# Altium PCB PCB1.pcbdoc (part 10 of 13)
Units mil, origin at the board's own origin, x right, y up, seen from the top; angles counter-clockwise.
Board outline 5895.51 x 5895.51 mil, 8 copper layers (Top Layer, L2_GND1, L3_SIG1, L4_GND2, L5_PWR, L6_SIG2, L7_GND3, Bottom Layer), stack 63.761 mil thick; 673 components, 558 nets, 2797 pads, 1861 vias.
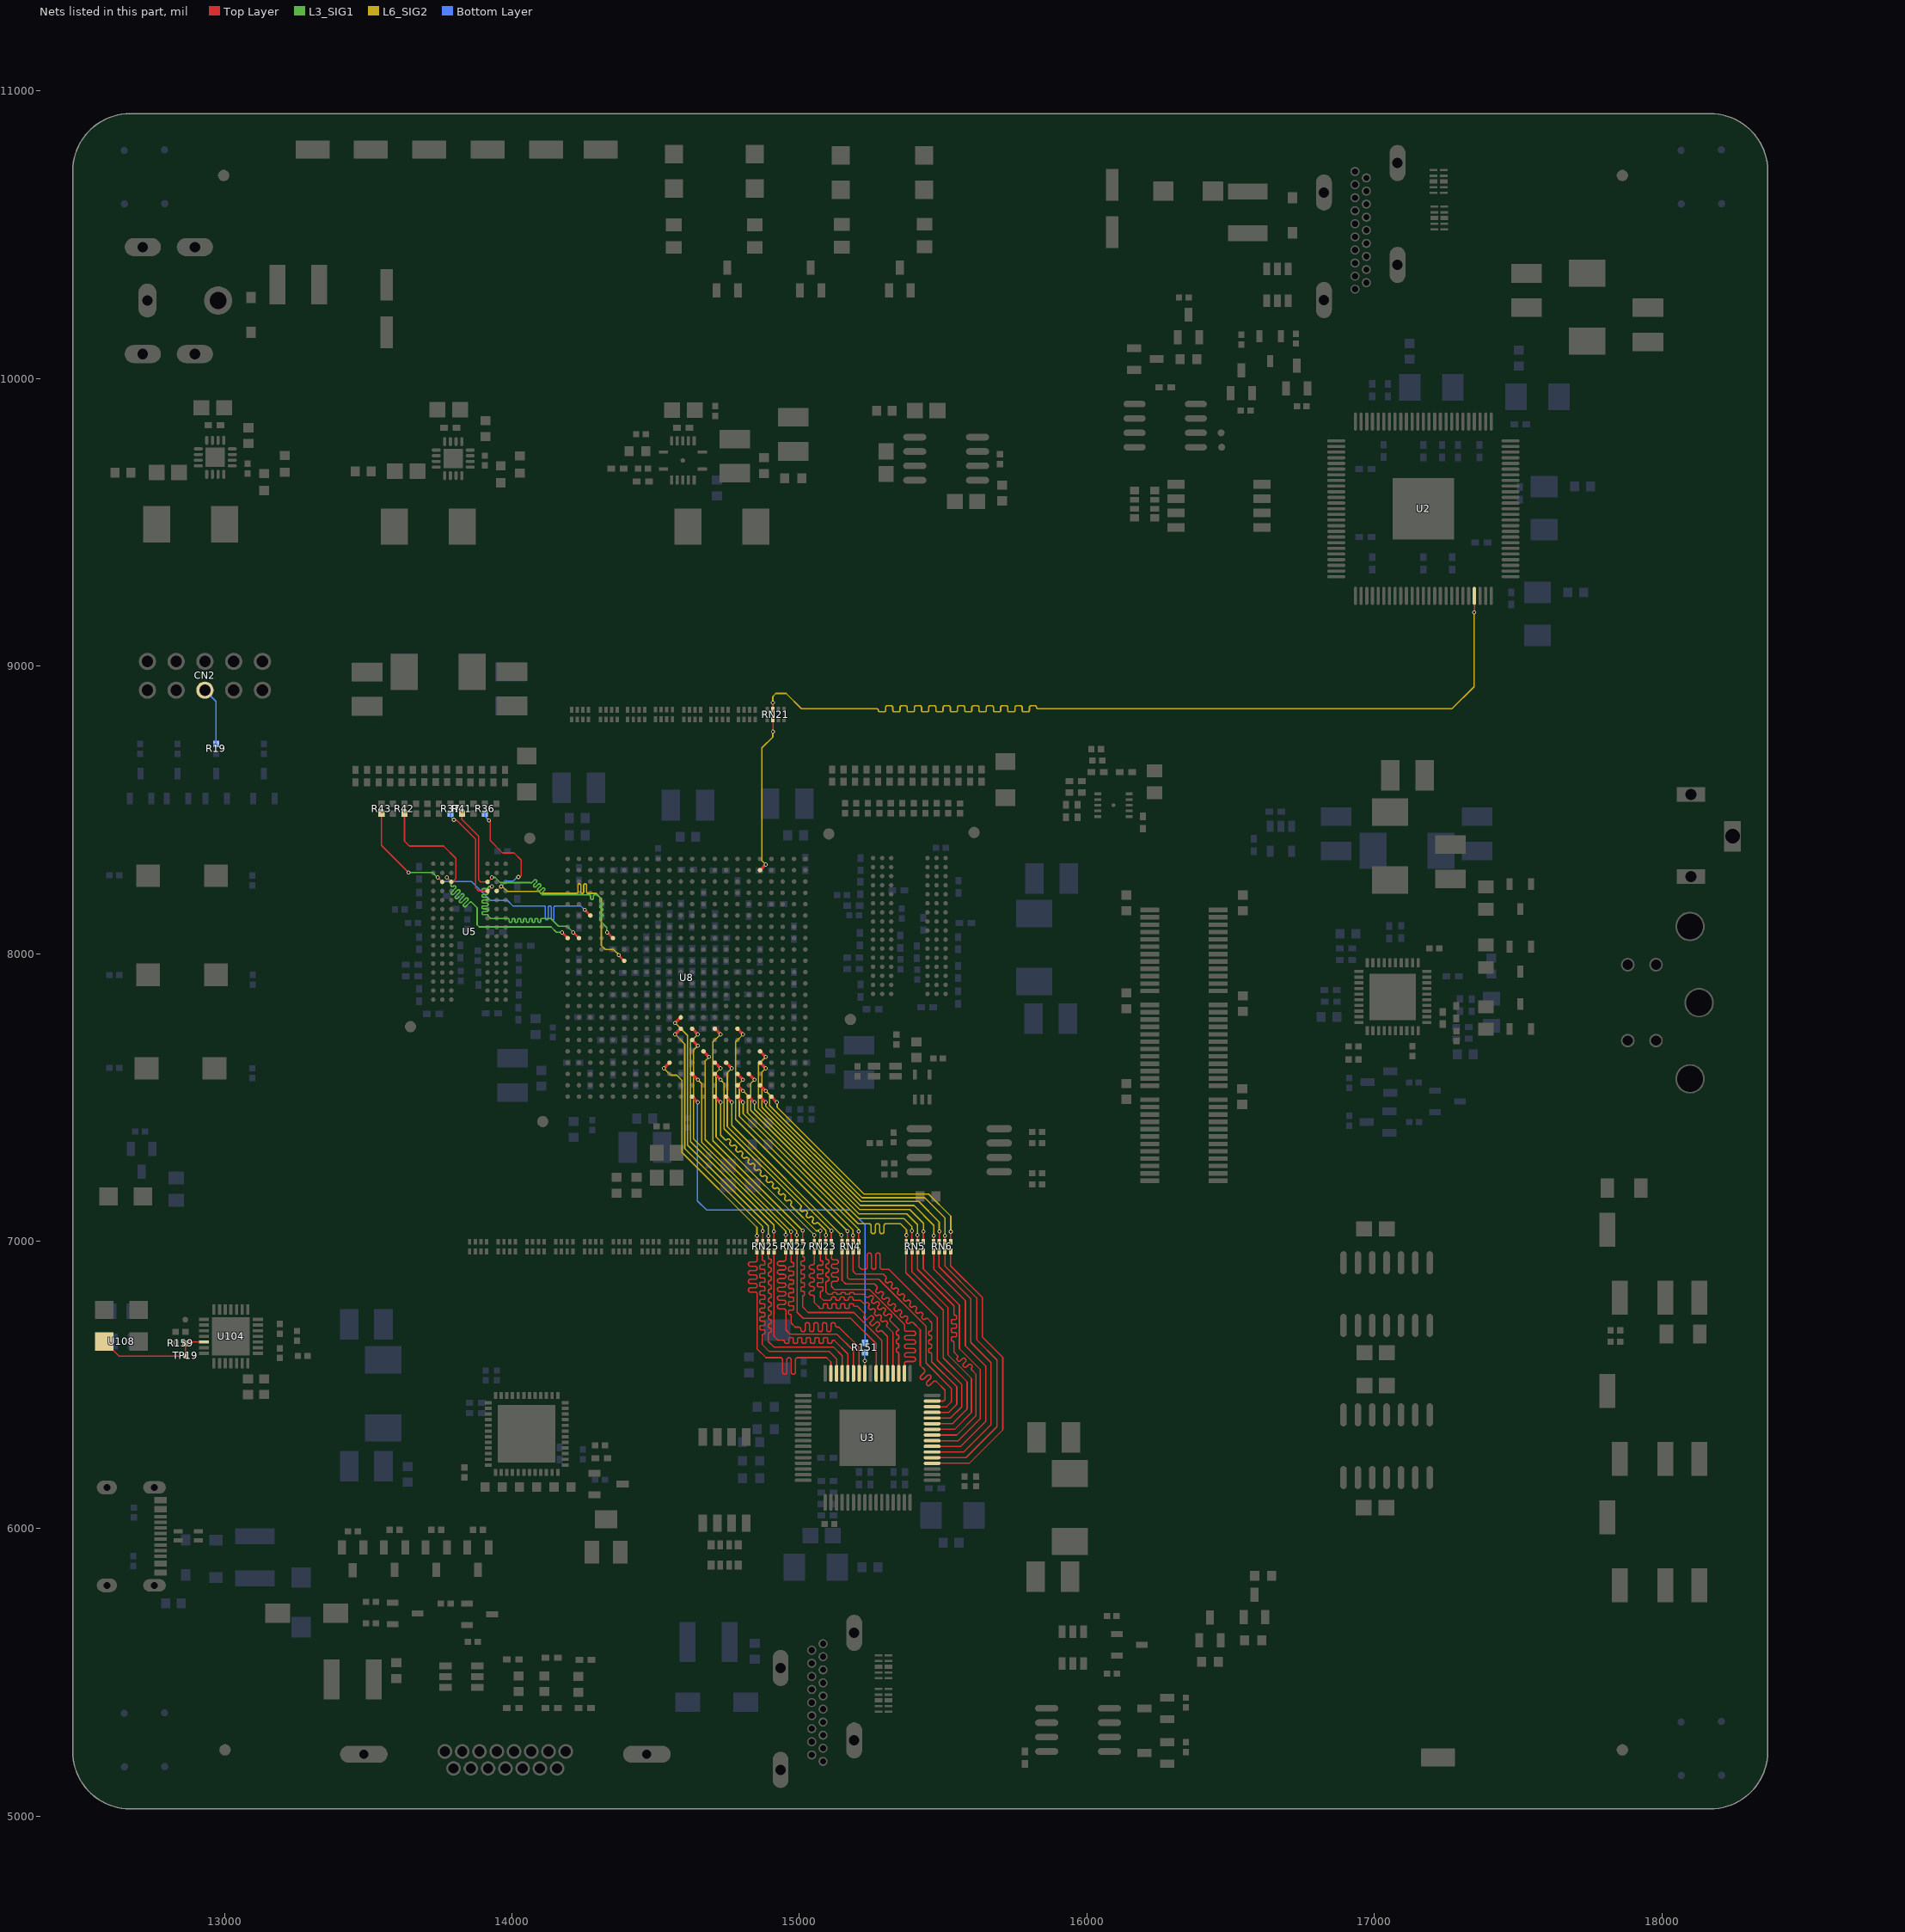
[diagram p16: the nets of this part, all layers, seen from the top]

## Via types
v1: diameter 23.62, hole 15.75, Top Layer to Bottom Layer, 621 vias
v2: diameter 13.8, hole 7.9, Top Layer to Bottom Layer, 567 vias
v3: diameter 13.78, hole 7.87, Top Layer to Bottom Layer, 529 vias
v4: diameter 13.78, hole 7.9, Top Layer to Bottom Layer, 114 vias
v5: diameter 15.75, hole 7.87, Top Layer to Bottom Layer, 16 vias
v6: diameter 24, hole 12, Top Layer to Bottom Layer, 10 vias
v7: diameter 11.81, hole 7.87, Top Layer to Bottom Layer, 4 vias

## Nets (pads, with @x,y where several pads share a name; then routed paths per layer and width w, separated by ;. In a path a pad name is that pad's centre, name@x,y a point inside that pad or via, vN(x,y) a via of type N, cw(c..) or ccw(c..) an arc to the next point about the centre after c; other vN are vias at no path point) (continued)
TFP401_VSYNC: RN21.6 U2.47 | length 3204.1
  Top Layer w4.7: RN21.6@14907.52,8847.83 v3(14907.52,8873) ; v4(17346.36,9187) 17348.01,9188.65 U2.47@17348.01,9232.15
  L6_SIG2 w5: v3(14907.52,8873) 14907.52,8893.88 14918.08,8904.44 14953.96,8904.44 15007.24,8851.17 15269.64,8851.17 cw(c15269.64,8845.96) 15274.85,8845.96 ccw(c15280.06,8845.96) 15280.06,8840.74 15294.64,8840.74 ccw(c15294.64,8845.96) 15299.85,8845.96 15299.85,8856.38 cw(c15305.06,8856.38) 15305.06,8861.59 15319.64,8861.59 cw(c15319.64,8856.38) 15324.85,8856.38 15324.85,8845.96 ccw(c15330.06,8845.96) 15330.06,8840.74 15344.64,8840.74 ccw(c15344.64,8845.96) 15349.85,8845.96 15349.85,8856.38 cw(c15355.06,8856.38) 15355.06,8861.59 15369.64,8861.59 cw(c15369.64,8856.38) 15374.85,8856.38 15374.85,8845.96 ccw(c15380.06,8845.96) 15380.06,8840.74 15394.64,8840.74 ccw(c15394.64,8845.96) 15399.85,8845.96 15399.85,8856.38 cw(c15405.06,8856.38) 15405.06,8861.59 15419.64,8861.59 cw(c15419.64,8856.38) 15424.85,8856.38 15424.85,8845.96 ccw(c15430.06,8845.96) 15430.06,8840.74 15444.64,8840.74 ccw(c15444.64,8845.96) 15449.85,8845.96 15449.85,8856.38 cw(c15455.06,8856.38) 15455.06,8861.59 15469.64,8861.59 cw(c15469.64,8856.38) 15474.85,8856.38 15474.85,8845.96 ccw(c15480.06,8845.96) 15480.06,8840.74 15494.64,8840.74 ccw(c15494.64,8845.96) 15499.85,8845.96 15499.85,8856.38 cw(c15505.06,8856.38) 15505.06,8861.59 15519.64,8861.59 cw(c15519.64,8856.38) 15524.85,8856.38 15524.85,8845.96 ccw(c15530.06,8845.96) 15530.06,8840.74 15544.64,8840.74 ccw(c15544.64,8845.96) 15549.85,8845.96 15549.85,8856.38 cw(c15555.06,8856.38) 15555.06,8861.59 15569.64,8861.59 cw(c15569.64,8856.38) 15574.85,8856.38 15574.85,8845.96 ccw(c15580.06,8845.96) 15580.06,8840.74 15594.64,8840.74 ccw(c15594.64,8845.96) 15599.85,8845.96 15599.85,8856.38 cw(c15605.06,8856.38) 15605.06,8861.59 15619.64,8861.59 cw(c15619.64,8856.38) 15624.85,8856.38 15624.85,8845.96 ccw(c15630.06,8845.96) 15630.06,8840.74 15644.64,8840.74 ccw(c15644.64,8845.96) 15649.85,8845.96 15649.85,8856.38 cw(c15655.06,8856.38) 15655.06,8861.59 15669.64,8861.59 cw(c15669.64,8856.38) 15674.85,8856.38 15674.85,8845.96 ccw(c15680.06,8845.96) 15680.06,8840.74 15694.64,8840.74 ccw(c15694.64,8845.96) 15699.85,8845.96 15699.85,8856.38 cw(c15705.06,8856.38) 15705.06,8861.59 15719.64,8861.59 cw(c15719.64,8856.38) 15724.85,8856.38 15724.85,8845.96 ccw(c15730.06,8845.96) 15730.06,8840.74 15744.64,8840.74 ccw(c15744.64,8845.96) 15749.85,8845.96 15749.85,8856.38 cw(c15755.06,8856.38) 15755.06,8861.59 15769.64,8861.59 cw(c15769.64,8856.38) 15774.85,8856.38 15774.85,8845.96 ccw(c15780.06,8845.96) 15780.06,8840.74 15794.64,8840.74 ccw(c15794.64,8845.96) 15799.85,8845.96 15799.85,8856.38 cw(c15805.06,8856.38) 15805.06,8861.59 15819.64,8861.59 cw(c15819.64,8856.38) 15824.85,8856.38 ccw(c15830.06,8856.38) 15830.06,8851.17 17269.84,8851.17 17346.48,8927.81 17346.48,8961.68 17346.36,8961.81 ; 17346.27,8961.9 17346.36,8961.81 ; v4(17346.36,9187) 17346.36,8961.81
TFP401_VSYNC_FPGA: RN21.3 U8.B18 | length 553.7
  Top Layer w4.7: RN21.3@14907.52,8814.17 14907.75,8813.93 v3(14907.75,8771.68)
  Top Layer w10: U8.B18@14863.26,8290.01 v2(14882.94,8309.69)
  L6_SIG2 w5: v2(14882.94,8309.69) 14869.67,8322.96 14869.67,8715.65 14907.41,8753.39 14907.41,8771.34 v3(14907.75,8771.68)
TFP410_CLK: R151.1 U3.57 | length 72.8
  Top Layer w4.7: U3.57@15225.56,6541.29 15227.36,6543.08 v3(15227.36,6584)
  Bottom Layer w4.7: v3(15227.36,6584) 15227.36,6611.96 R151.1@15228.36,6612.96
TFP410_CLK_FPGA: R151.2 U8.AB12 | length 1398.7
  Top Layer w10: U8.AB12@14627.06,7502.6 v2(14646.74,7482.92)
  Bottom Layer w4.7: v2(14646.74,7482.92) 14645.36,7481.54 14645.36,7140 14676.36,7109 15176.36,7109 15228.36,7057 R151.2@15228.36,6647.04
TFP410_D0: RN25.8 U3.63 | length 1056
  Top Layer w4.7: RN25.8@14852.83,6964.17 14853.36,6963.64 14853.36,6935.12 cw(c14845.86,6935.12) 14845.86,6927.62 14829.86,6927.62 ccw(c14829.86,6920.12) 14829.86,6912.62 14845.86,6912.62 cw(c14845.86,6905.12) 14845.86,6897.62 14829.86,6897.62 ccw(c14829.86,6890.12) 14829.86,6882.62 14845.86,6882.62 cw(c14845.86,6875.12) 14845.86,6867.62 14829.86,6867.62 ccw(c14829.86,6860.12) 14829.86,6852.62 14845.86,6852.62 cw(c14845.86,6845.12) 14845.86,6837.62 14829.86,6837.62 ccw(c14829.86,6830.12) 14829.86,6822.62 14845.86,6822.62 cw(c14845.86,6815.12) 14853.36,6815.12 14853.36,6625 14883.36,6595 14933.74,6595 cw(c14933.74,6587.5) 14941.24,6587.5 14941.24,6544.59 ccw(c14948.74,6544.59) 14956.24,6544.59 14956.24,6587.5 cw(c14963.74,6587.5) 14971.24,6587.5 14971.24,6544.59 ccw(c14978.74,6544.59) 14986.24,6544.59 14986.24,6587.5 cw(c14993.74,6587.5) 14993.74,6595 15094.36,6595 15109.41,6579.95 U3.63@15109.41,6540.41
TFP410_D0_FPGA: RN25.1 U8.W10 | length 777.4
  Top Layer w4.7: v3(14852.36,7019) 14852.83,7018.53 RN25.1@14852.83,6997.83
  Top Layer w10: v2(14528.63,7601.05) U8.W10@14548.3,7620.73
  L6_SIG2 w5: v2(14528.63,7601.05) 14552.68,7577 14573.36,7577 14591.36,7559 14591.36,7309 14852.36,7048 v3(14852.36,7019)
TFP410_D1: RN25.7 U3.62 | length 889.9
  Top Layer w4.7: RN25.7@14872.52,6964.17 14871.36,6963.01 14871.36,6936.43 ccw(c14875.86,6936.43) 14875.86,6931.93 cw(c14875.86,6927.43) 14880.36,6927.43 14880.36,6921.43 cw(c14875.86,6921.43) 14875.86,6916.93 14866.86,6916.93 ccw(c14866.86,6912.43) 14862.36,6912.43 14862.36,6906.43 ccw(c14866.86,6906.43) 14866.86,6901.93 14875.86,6901.93 cw(c14875.86,6897.43) 14880.36,6897.43 14880.36,6891.43 cw(c14875.86,6891.43) 14875.86,6886.93 14866.86,6886.93 ccw(c14866.86,6882.43) 14862.36,6882.43 14862.36,6876.43 ccw(c14866.86,6876.43) 14866.86,6871.93 14875.86,6871.93 cw(c14875.86,6867.43) 14880.36,6867.43 14880.36,6861.43 cw(c14875.86,6861.43) 14875.86,6856.93 14866.86,6856.93 ccw(c14866.86,6852.43) 14862.36,6852.43 14862.36,6846.43 ccw(c14866.86,6846.43) 14866.86,6841.93 14875.86,6841.93 cw(c14875.86,6837.43) 14880.36,6837.43 14880.36,6831.43 cw(c14875.86,6831.43) 14875.86,6826.93 14866.86,6826.93 ccw(c14866.86,6822.43) 14862.36,6822.43 14862.36,6816.43 ccw(c14866.86,6816.43) 14866.86,6811.93 14875.86,6811.93 cw(c14875.86,6807.43) 14880.36,6807.43 14880.36,6801.43 cw(c14875.86,6801.43) 14875.86,6796.93 14866.86,6796.93 ccw(c14866.86,6792.43) 14862.36,6792.43 14862.36,6786.43 ccw(c14866.86,6786.43) 14866.86,6781.93 14875.86,6781.93 cw(c14875.86,6777.43) 14880.36,6777.43 14880.36,6771.43 cw(c14875.86,6771.43) 14875.86,6766.93 14866.86,6766.93 ccw(c14866.86,6762.43) 14862.36,6762.43 14862.36,6756.43 ccw(c14866.86,6756.43) 14866.86,6751.93 14875.86,6751.93 cw(c14875.86,6747.43) 14880.36,6747.43 14880.36,6741.43 cw(c14875.86,6741.43) 14875.86,6736.93 14866.86,6736.93 ccw(c14866.86,6732.43) 14862.36,6732.43 14862.36,6726.43 ccw(c14866.86,6726.43) 14866.86,6721.93 14875.86,6721.93 cw(c14875.86,6717.43) 14880.36,6717.43 14880.36,6711.43 cw(c14875.86,6711.43) 14875.86,6706.93 14866.86,6706.93 ccw(c14866.86,6702.43) 14862.36,6702.43 14862.36,6696.43 ccw(c14866.86,6696.43) 14866.86,6691.93 14875.86,6691.93 cw(c14875.86,6687.43) 14880.36,6687.43 14880.36,6681.43 cw(c14875.86,6681.43) 14875.86,6676.93 ccw(c14875.86,6672.43) 14871.36,6672.43 14871.36,6640 14895.36,6616 15104.36,6616 15129.09,6591.27 U3.62@15129.09,6540.41
TFP410_D1_FPGA: RN25.2 U8.T11 | length 875.3
  Top Layer w4.7: v3(14872.36,7035) 14872.52,7034.84 RN25.2@14872.52,6997.83
  Top Layer w10: v2(14567.99,7719.16) U8.T11@14587.66,7738.84
  L6_SIG2 w5: v2(14567.99,7719.16) 14601.36,7685.79 14601.36,7322 14872.36,7051 v3(14872.36,7035)
TFP410_D2: RN25.6 U3.61 | length 755.7
  Top Layer w4.7: RN25.6@14892.2,6964.17 14892.2,6942.86 ccw(c14897.28,6942.86) 14897.28,6937.78 cw(c14897.28,6932.7) 14902.36,6932.7 14902.36,6927.86 cw(c14897.28,6927.86) 14897.28,6922.78 ccw(c14897.28,6917.7) 14892.2,6917.7 14892.2,6912.86 ccw(c14897.28,6912.86) 14897.28,6907.78 cw(c14897.28,6902.7) 14902.36,6902.7 14902.36,6897.86 cw(c14897.28,6897.86) 14897.28,6892.78 ccw(c14897.28,6887.7) 14892.2,6887.7 14892.2,6882.86 ccw(c14897.28,6882.86) 14897.28,6877.78 cw(c14897.28,6872.7) 14902.36,6872.7 14902.36,6867.86 cw(c14897.28,6867.86) 14897.28,6862.78 ccw(c14897.28,6857.7) 14892.2,6857.7 14892.2,6852.86 ccw(c14897.28,6852.86) 14897.28,6847.78 cw(c14897.28,6842.7) 14902.36,6842.7 14902.36,6837.86 cw(c14897.28,6837.86) 14897.28,6832.78 ccw(c14897.28,6827.7) 14892.2,6827.7 14892.2,6822.86 ccw(c14897.28,6822.86) 14897.28,6817.78 cw(c14897.28,6812.7) 14902.36,6812.7 14902.36,6807.86 cw(c14897.28,6807.86) 14897.28,6802.78 ccw(c14897.28,6797.7) 14892.2,6797.7 14892.2,6792.86 ccw(c14897.28,6792.86) 14897.28,6787.78 cw(c14897.28,6782.7) 14902.36,6782.7 14902.36,6777.86 cw(c14897.28,6777.86) 14897.28,6772.78 ccw(c14897.28,6767.7) 14892.2,6767.7 14892.2,6762.86 ccw(c14897.28,6762.86) 14897.28,6757.78 cw(c14897.28,6752.7) 14902.36,6752.7 14902.36,6747.86 cw(c14897.28,6747.86) 14897.28,6742.78 ccw(c14897.28,6737.7) 14892.2,6737.7 14892.2,6732.86 ccw(c14897.28,6732.86) 14897.28,6727.78 cw(c14897.28,6722.7) 14902.36,6722.7 14902.36,6717.86 cw(c14897.28,6717.86) 14897.28,6712.78 ccw(c14897.28,6707.7) 14892.2,6707.7 14892.2,6702.86 ccw(c14897.28,6702.86) 14897.28,6697.78 cw(c14897.28,6692.7) 14902.36,6692.7 14902.36,6687.86 cw(c14897.28,6687.86) 14897.28,6682.78 ccw(c14897.28,6677.7) 14892.2,6677.7 14892.2,6651.16 14911.36,6632 15118.36,6632 15148.78,6601.58 U3.61@15148.78,6540.41
TFP410_D2_FPGA: RN25.3 U8.R11 | length 922.9
  Top Layer w4.7: RN25.3@14892.2,6997.83 14892.2,7017.84 v3(14892.36,7018)
  Top Layer w10: v2(14567.99,7758.52) U8.R11@14587.66,7778.2
  L6_SIG2 w5: v2(14567.99,7758.52) 14611.26,7715.25 14611.26,7334.1 14892.36,7053 v3(14892.36,7018)
TFP410_D3: RN25.5 U3.60 | length 812.8
  Top Layer w4.7: RN25.5@14911.89,6964.17 14911.89,6669.47 14926.36,6655 14943.41,6655 cw(c14943.41,6650) 14948.41,6650 ccw(c14953.41,6650) 14953.41,6645 14958.41,6645 ccw(c14958.41,6650) 14963.41,6650 14963.41,6660 cw(c14968.41,6660) 14968.41,6665 14973.41,6665 cw(c14973.41,6660) 14978.41,6660 14978.41,6650 ccw(c14983.41,6650) 14983.41,6645 14988.41,6645 ccw(c14988.41,6650) 14993.41,6650 14993.41,6660 cw(c14998.41,6660) 14998.41,6665 15003.41,6665 cw(c15003.41,6660) 15008.41,6660 15008.41,6650 ccw(c15013.41,6650) 15013.41,6645 15018.41,6645 ccw(c15018.41,6650) 15023.41,6650 15023.41,6660 cw(c15028.41,6660) 15028.41,6665 15033.41,6665 cw(c15033.41,6660) 15038.41,6660 15038.41,6650 ccw(c15043.41,6650) 15043.41,6645 15048.41,6645 ccw(c15048.41,6650) 15053.41,6650 15053.41,6660 cw(c15058.41,6660) 15058.41,6665 15063.41,6665 cw(c15063.41,6660) 15068.41,6660 15068.41,6650 ccw(c15073.41,6650) 15073.41,6645 15078.41,6645 ccw(c15078.41,6650) 15083.41,6650 15083.41,6660 cw(c15088.41,6660) 15088.41,6665 15093.41,6665 cw(c15093.41,6660) 15098.41,6660 15098.41,6650 ccw(c15103.41,6650) 15103.41,6645 15108.41,6645 ccw(c15108.41,6650) 15113.41,6650 cw(c15118.41,6650) 15118.41,6655 15121.36,6655 15168.36,6608 15168.36,6540.51 U3.60@15168.46,6540.41
TFP410_D3_FPGA: RN25.4 U8.T12 | length 880
  Top Layer w4.7: v3(14911.36,7034) 14911.89,7033.47 RN25.4@14911.89,6997.83
  Top Layer w10: U8.T12@14627.06,7738.84 v2(14646.74,7719.16)
  L6_SIG2 w5: v2(14646.74,7719.16) 14621.36,7693.78 14621.36,7346 14911.36,7056 v3(14911.36,7034)
TFP410_D4: RN27.8 U3.59 | length 893.1
  Top Layer w4.7: RN27.8@14952.83,6964.17 14952.83,6937.39 cw(c14945.33,6937.39) 14945.33,6929.89 14930.86,6929.89 ccw(c14930.86,6922.39) 14930.86,6914.89 14945.33,6914.89 cw(c14945.33,6907.39) 14945.33,6899.89 14930.86,6899.89 ccw(c14930.86,6892.39) 14930.86,6884.89 14945.33,6884.89 cw(c14945.33,6877.39) 14945.33,6869.89 14930.86,6869.89 ccw(c14930.86,6862.39) 14930.86,6854.89 14945.33,6854.89 cw(c14945.33,6847.39) 14945.33,6839.89 14930.86,6839.89 ccw(c14930.86,6832.39) 14930.86,6824.89 14945.33,6824.89 cw(c14945.33,6817.39) 14945.33,6809.89 14930.86,6809.89 ccw(c14930.86,6802.39) 14930.86,6794.89 14945.33,6794.89 cw(c14945.33,6787.39) 14945.33,6779.89 14930.86,6779.89 ccw(c14930.86,6772.39) 14930.86,6764.89 14945.33,6764.89 cw(c14945.33,6757.39) 14952.83,6757.39 14952.83,6691.53 14968.36,6676 15131.36,6676 15188.15,6619.21 U3.59@15188.15,6540.41
TFP410_D4_FPGA: RN27.1 U8.U12 | length 849.3
  Top Layer w4.7: RN27.1@14951.83,6997.83 14951.83,7021.47 v3(14952.36,7022)
  Top Layer w10: U8.U12@14627.06,7699.47 v2(14646.74,7679.79)
  L6_SIG2 w5: v2(14646.74,7679.79) 14631.36,7664.41 14631.36,7356 14952.36,7035 v3(14952.36,7022)
TFP410_D5: RN27.7 U3.58 | length 975.1
  Top Layer w4.7: RN27.7@14972.52,6964.17 14971.36,6963.01 14971.36,6930.06 ccw(c14975.86,6930.06) 14975.86,6925.56 cw(c14975.86,6921.06) 14980.36,6921.06 14980.36,6915.06 cw(c14975.86,6915.06) 14975.86,6910.56 14966.86,6910.56 ccw(c14966.86,6906.06) 14962.36,6906.06 14962.36,6900.06 ccw(c14966.86,6900.06) 14966.86,6895.56 14975.86,6895.56 cw(c14975.86,6891.06) 14980.36,6891.06 14980.36,6885.06 cw(c14975.86,6885.06) 14975.86,6880.56 14966.86,6880.56 ccw(c14966.86,6876.06) 14962.36,6876.06 14962.36,6870.06 ccw(c14966.86,6870.06) 14966.86,6865.56 14975.86,6865.56 cw(c14975.86,6861.06) 14980.36,6861.06 14980.36,6855.06 cw(c14975.86,6855.06) 14975.86,6850.56 14966.86,6850.56 ccw(c14966.86,6846.06) 14962.36,6846.06 14962.36,6840.06 ccw(c14966.86,6840.06) 14966.86,6835.56 14975.86,6835.56 cw(c14975.86,6831.06) 14980.36,6831.06 14980.36,6825.06 cw(c14975.86,6825.06) 14975.86,6820.56 14966.86,6820.56 ccw(c14966.86,6816.06) 14962.36,6816.06 14962.36,6810.06 ccw(c14966.86,6810.06) 14966.86,6805.56 14975.86,6805.56 cw(c14975.86,6801.06) 14980.36,6801.06 14980.36,6795.06 cw(c14975.86,6795.06) 14975.86,6790.56 14966.86,6790.56 ccw(c14966.86,6786.06) 14962.36,6786.06 14962.36,6780.06 ccw(c14966.86,6780.06) 14966.86,6775.56 14975.86,6775.56 cw(c14975.86,6771.06) 14980.36,6771.06 14980.36,6765.06 cw(c14975.86,6765.06) 14975.86,6760.56 14966.86,6760.56 ccw(c14966.86,6756.06) 14962.36,6756.06 14962.36,6750.06 ccw(c14966.86,6750.06) 14966.86,6745.56 cw(c14966.86,6741.06) 14971.36,6741.06 14971.36,6715 14985.36,6701 14997.51,6701 cw(c14997.51,6693.5) 15005.01,6693.5 15005.01,6692.5 ccw(c15012.51,6692.5) 15020.01,6692.5 15020.01,6709.5 cw(c15027.51,6709.5) 15035.01,6709.5 15035.01,6692.5 ccw(c15042.51,6692.5) 15050.01,6692.5 15050.01,6709.5 cw(c15057.51,6709.5) 15065.01,6709.5 15065.01,6692.5 ccw(c15072.51,6692.5) 15080.01,6692.5 15080.01,6709.5 cw(c15087.51,6709.5) 15095.01,6709.5 15095.01,6692.5 ccw(c15102.51,6692.5) 15110.01,6692.5 15110.01,6709.5 cw(c15117.51,6709.5) 15125.01,6709.5 15125.01,6708.5 ccw(c15132.51,6708.5) 15132.51,6701 15137.36,6701 15207.83,6630.53 U3.58@15207.83,6540.41
TFP410_D5_FPGA: RN27.2 U8.Y12 | length 726.2
  Top Layer w4.7: v3(14971.36,7033) 14971.52,7032.84 RN27.2@14971.52,6997.83
  Top Layer w10: U8.Y12@14627.06,7581.35 v2(14646.74,7561.68)
  L6_SIG2 w5: v2(14646.74,7561.68) 14660.36,7548.06 14660.36,7344 v3(14971.36,7033)
TFP410_D6: RN27.6 U3.55 | length 634.2
  Top Layer w4.7: RN27.6@14992.2,6964.17 14992.36,6964.01 14992.36,6753 15013.36,6732 15178.36,6732 15266.89,6643.47 U3.55@15266.89,6540.41
TFP410_D6_FPGA: RN27.3 U8.V13 | length 808.2
  Top Layer w4.7: v3(14990.36,7021) 14990.36,6998.67 RN27.3@14991.2,6997.83
  Top Layer w10: U8.V13@14666.41,7660.1 v2(14686.09,7640.42)
  L6_SIG2 w5: v2(14686.09,7640.42) 14672.36,7626.69 14672.36,7354 14990.36,7036 v3(14990.36,7021)
TFP410_D7: RN27.5 U3.54 | length 706.5
  Top Layer w4.7: RN27.5@15011.89,6964.17 15011.36,6963.64 15011.36,6948.39 ccw(c15014.11,6948.39) 15014.11,6945.64 cw(c15014.11,6942.89) 15016.86,6942.89 15016.86,6933.39 cw(c15014.11,6933.39) 15014.11,6930.64 15008.61,6930.64 ccw(c15008.61,6927.89) 15005.86,6927.89 15005.86,6918.39 ccw(c15008.61,6918.39) 15008.61,6915.64 15014.11,6915.64 cw(c15014.11,6912.89) 15016.86,6912.89 15016.86,6903.39 cw(c15014.11,6903.39) 15014.11,6900.64 15008.61,6900.64 ccw(c15008.61,6897.89) 15005.86,6897.89 15005.86,6888.39 ccw(c15008.61,6888.39) 15008.61,6885.64 15014.11,6885.64 cw(c15014.11,6882.89) 15016.86,6882.89 15016.86,6873.39 cw(c15014.11,6873.39) 15014.11,6870.64 15008.61,6870.64 ccw(c15008.61,6867.89) 15005.86,6867.89 15005.86,6858.39 ccw(c15008.61,6858.39) 15008.61,6855.64 15014.11,6855.64 cw(c15014.11,6852.89) 15016.86,6852.89 15016.86,6843.39 cw(c15014.11,6843.39) 15014.11,6840.64 15008.61,6840.64 ccw(c15008.61,6837.89) 15005.86,6837.89 15005.86,6828.39 ccw(c15008.61,6828.39) 15008.61,6825.64 15014.11,6825.64 cw(c15014.11,6822.89) 15016.86,6822.89 15016.86,6813.39 cw(c15014.11,6813.39) 15014.11,6810.64 ccw(c15014.11,6807.89) 15011.36,6807.89 15011.36,6771 15030.36,6752 15189.36,6752 15286.57,6654.79 U3.54@15286.57,6540.41
TFP410_D7_FPGA: RN27.4 U8.T14 | length 889.4
  Top Layer w4.7: RN27.4@15010.89,6997.83 15010.89,7036.53 v3(15011.36,7037)
  Top Layer w10: U8.T14@14705.78,7738.84 v2(14725.46,7719.16)
  L6_SIG2 w5: v2(14725.46,7719.16) 14699.36,7693.06 14699.36,7349 v3(15011.36,7037)
TFP410_D8: RN23.8 U3.53 | length 893.5
  Top Layer w4.7: RN23.8@15052.83,6964.17 15052.36,6963.7 15052.36,6924.72 cw(c15044.86,6924.72) 15044.86,6917.22 15041.86,6917.22 ccw(c15041.86,6909.72) 15041.86,6902.22 15044.86,6902.22 cw(c15044.86,6894.72) 15044.86,6887.22 15041.86,6887.22 ccw(c15041.86,6879.72) 15041.86,6872.22 15044.86,6872.22 cw(c15044.86,6864.72) 15044.86,6857.22 15041.86,6857.22 ccw(c15041.86,6849.72) 15041.86,6842.22 15044.86,6842.22 cw(c15044.86,6834.72) 15044.86,6827.22 15041.86,6827.22 ccw(c15041.86,6819.72) 15041.86,6812.22 15044.86,6812.22 cw(c15044.86,6804.72) 15052.36,6804.72 15052.36,6786 15064.36,6774 cw(c15064.36,6770) 15068.36,6770 ccw(c15072.36,6770) 15072.36,6766 15079.36,6766 ccw(c15079.36,6770) 15083.36,6770 15083.36,6778 cw(c15087.36,6778) 15087.36,6782 15094.36,6782 cw(c15094.36,6778) 15098.36,6778 15098.36,6770 ccw(c15102.36,6770) 15102.36,6766 15109.36,6766 ccw(c15109.36,6770) 15113.36,6770 15113.36,6778 cw(c15117.36,6778) 15117.36,6782 15124.36,6782 cw(c15124.36,6778) 15128.36,6778 15128.36,6770 ccw(c15132.36,6770) 15132.36,6766 15139.36,6766 ccw(c15139.36,6770) 15143.36,6770 15143.36,6778 cw(c15147.36,6778) 15147.36,6782 15154.36,6782 cw(c15154.36,6778) 15158.36,6778 15158.36,6770 ccw(c15162.36,6770) 15162.36,6766 15169.36,6766 ccw(c15169.36,6770) 15173.36,6770 15173.36,6778 cw(c15177.36,6778) 15177.36,6782 15184.36,6782 cw(c15184.36,6778) 15188.36,6778 ccw(c15192.36,6778) 15192.36,6774 15201.36,6774 15226.14,6749.22 cw(c15221.64,6744.72) 15226.14,6740.22 ccw(c15230.64,6735.72) 15226.14,6731.22 15227.75,6729.61 ccw(c15232.25,6734.11) 15236.75,6729.61 15245.75,6738.61 cw(c15250.25,6734.11) 15254.75,6738.61 15256.35,6737 cw(c15251.85,6732.5) 15256.35,6728 15247.35,6719 ccw(c15251.85,6714.5) 15247.35,6710 15248.96,6708.4 ccw(c15253.46,6712.9) 15257.96,6708.4 15266.96,6717.4 cw(c15271.46,6712.9) 15275.96,6717.4 15277.57,6715.79 cw(c15273.07,6711.29) 15277.57,6706.79 15268.57,6697.79 ccw(c15273.07,6693.29) 15268.57,6688.79 15270.17,6687.18 ccw(c15274.67,6691.68) 15279.17,6687.18 cw(c15283.67,6682.68) 15288.17,6687.18 15306.26,6669.1 U3.53@15306.26,6540.41
TFP410_D8_FPGA: RN23.1 U8.W14 | length 779.2
  Top Layer w4.7: RN23.1@15051.83,6997.83 15051.83,7020.47 v3(15052.36,7021)
  Top Layer w10: U8.W14@14705.78,7620.73 v2(14725.46,7601.05)
  L6_SIG2 w5: v2(14725.46,7601.05) 14710.36,7585.95 14710.36,7363 v3(15052.36,7021)
TFP410_D9: RN23.7 U3.52 | length 806.1
  Top Layer w4.7: RN23.7@15072.52,6964.17 15072.36,6964.01 15072.36,6936.24 ccw(c15077.36,6936.24) 15077.36,6931.24 cw(c15077.36,6926.24) 15082.36,6926.24 15082.36,6921.24 cw(c15077.36,6921.24) 15077.36,6916.24 15067.36,6916.24 ccw(c15067.36,6911.24) 15062.36,6911.24 15062.36,6906.24 ccw(c15067.36,6906.24) 15067.36,6901.24 15077.36,6901.24 cw(c15077.36,6896.24) 15082.36,6896.24 15082.36,6891.24 cw(c15077.36,6891.24) 15077.36,6886.24 15067.36,6886.24 ccw(c15067.36,6881.24) 15062.36,6881.24 15062.36,6876.24 ccw(c15067.36,6876.24) 15067.36,6871.24 15077.36,6871.24 cw(c15077.36,6866.24) 15082.36,6866.24 15082.36,6861.24 cw(c15077.36,6861.24) 15077.36,6856.24 15067.36,6856.24 ccw(c15067.36,6851.24) 15062.36,6851.24 15062.36,6846.24 ccw(c15067.36,6846.24) 15067.36,6841.24 15077.36,6841.24 cw(c15077.36,6836.24) 15082.36,6836.24 15082.36,6831.24 cw(c15077.36,6831.24) 15077.36,6826.24 ccw(c15077.36,6821.24) 15072.36,6821.24 15072.36,6806 15084.36,6794 15105.13,6794 ccw(c15105.13,6800) 15111.13,6800 cw(c15117.13,6800) 15117.13,6806 15120.13,6806 cw(c15120.13,6800) 15126.13,6800 ccw(c15132.13,6800) 15132.13,6794 15135.13,6794 ccw(c15135.13,6800) 15141.13,6800 cw(c15147.13,6800) 15147.13,6806 15150.13,6806 cw(c15150.13,6800) 15156.13,6800 ccw(c15162.13,6800) 15162.13,6794 15165.13,6794 ccw(c15165.13,6800) 15171.13,6800 cw(c15177.13,6800) 15177.13,6806 15180.13,6806 cw(c15180.13,6800) 15186.13,6800 ccw(c15192.13,6800) 15192.13,6794 15213.36,6794 15222.4,6784.96 ccw(c15226.65,6789.21) 15230.9,6784.96 cw(c15235.15,6780.71) 15239.4,6784.96 15241.51,6782.85 cw(c15237.26,6778.6) 15241.51,6774.35 ccw(c15245.76,6770.1) 15241.51,6765.85 15243.62,6763.74 ccw(c15247.87,6767.99) 15252.12,6763.74 cw(c15256.37,6759.49) 15260.62,6763.74 15262.72,6761.64 cw(c15258.47,6757.39) 15262.72,6753.14 ccw(c15266.97,6748.89) 15262.72,6744.64 15264.83,6742.53 ccw(c15269.08,6746.78) 15273.33,6742.53 cw(c15277.58,6738.28) 15281.83,6742.53 15283.94,6740.42 cw(c15279.69,6736.17) 15283.94,6731.92 ccw(c15288.19,6727.67) 15283.94,6723.42 15286.04,6721.32 ccw(c15290.29,6725.57) 15294.54,6721.32 cw(c15298.79,6717.07) 15303.04,6721.32 15305.15,6719.21 cw(c15300.9,6714.96) 15305.15,6710.71 ccw(c15309.4,6706.46) 15305.15,6702.21 15325.94,6681.42 U3.52@15325.94,6540.41
TFP410_D9_FPGA: RN23.2 U8.AB14 | length 807.2
  Top Layer w4.7: RN23.2@15071.52,6997.83 15071.52,7035.16 v3(15072.36,7036)
  Top Layer w10: U8.AB14@14705.78,7502.6 v2(14725.46,7482.92)
  L6_SIG2 w5: v2(14725.46,7482.92) 14725.46,7368.9 14740.53,7353.83 ccw(c14744.53,7357.83) 14748.53,7353.83 cw(c14752.53,7349.83) 14756.53,7353.83 14759.14,7351.22 cw(c14755.14,7347.22) 14759.14,7343.22 ccw(c14763.14,7339.22) 14759.14,7335.22 14761.74,7332.61 ccw(c14765.74,7336.61) 14769.74,7332.61 cw(c14773.74,7328.61) 14777.74,7332.61 14780.35,7330.01 cw(c14776.35,7326.01) 14780.35,7322.01 ccw(c14784.35,7318.01) 14780.35,7314.01 14782.96,7311.4 ccw(c14786.96,7315.4) 14790.96,7311.4 cw(c14794.96,7307.4) 14798.96,7311.4 14801.56,7308.79 cw(c14797.56,7304.79) 14801.56,7300.79 ccw(c14805.56,7296.79) 14801.56,7292.79 14804.17,7290.19 ccw(c14808.17,7294.19) 14812.17,7290.19 cw(c14816.17,7286.19) 14820.17,7290.19 14822.78,7287.58 cw(c14818.78,7283.58) 14822.78,7279.58 ccw(c14826.78,7275.58) 14822.78,7271.58 14825.38,7268.97 ccw(c14829.38,7272.97) 14833.38,7268.97 cw(c14837.38,7264.97) 14841.38,7268.97 14843.99,7266.37 cw(c14839.99,7262.37) 14843.99,7258.37 ccw(c14847.99,7254.37) 14843.99,7250.37 14846.6,7247.76 ccw(c14850.6,7251.76) 14854.6,7247.76 cw(c14858.6,7243.76) 14862.6,7247.76 14865.2,7245.15 cw(c14861.2,7241.15) 14865.2,7237.15 ccw(c14869.2,7233.15) 14865.2,7229.15 14867.81,7226.55 ccw(c14871.81,7230.55) 14875.81,7226.55 cw(c14879.81,7222.55) 14883.81,7226.55 14886.42,7223.94 cw(c14882.42,7219.94) 14886.42,7215.94 ccw(c14890.42,7211.94) 14886.42,7207.94 14889.02,7205.33 ccw(c14893.02,7209.33) 14897.02,7205.33 cw(c14901.02,7201.33) 14905.02,7205.33 14907.63,7202.73 cw(c14903.63,7198.73) 14907.63,7194.73 ccw(c14911.63,7190.73) 14907.63,7186.73 14910.24,7184.12 ccw(c14914.24,7188.12) 14918.24,7184.12 cw(c14922.24,7180.12) 14926.24,7184.12 14928.84,7181.51 cw(c14924.84,7177.51) 14928.84,7173.51 ccw(c14932.84,7169.51) 14928.84,7165.51 14931.45,7162.91 ccw(c14935.45,7166.91) 14939.45,7162.91 cw(c14943.45,7158.91) 14947.45,7162.91 14950.06,7160.3 cw(c14946.06,7156.3) 14950.06,7152.3 ccw(c14954.06,7148.3) 14950.06,7144.3 14952.66,7141.69 ccw(c14956.66,7145.69) 14960.66,7141.69 cw(c14964.66,7137.69) 14968.66,7141.69 14971.27,7139.09 cw(c14967.27,7135.09) 14971.27,7131.09 ccw(c14975.27,7127.09) 14971.27,7123.09 15058.36,7036 v3(15072.36,7036)
TFP410_D10: RN23.6 U3.51 | length 773.2
  Top Layer w4.7: RN23.6@15092.2,6964.17 15092.36,6964.01 15092.36,6940.98 ccw(c15097.36,6940.98) 15097.36,6935.98 cw(c15097.36,6930.98) 15102.36,6930.98 15102.36,6925.98 cw(c15097.36,6925.98) 15097.36,6920.98 ccw(c15097.36,6915.98) 15092.36,6915.98 15092.36,6910.98 ccw(c15097.36,6910.98) 15097.36,6905.98 cw(c15097.36,6900.98) 15102.36,6900.98 15102.36,6895.98 cw(c15097.36,6895.98) 15097.36,6890.98 ccw(c15097.36,6885.98) 15092.36,6885.98 15092.36,6880.98 ccw(c15097.36,6880.98) 15097.36,6875.98 cw(c15097.36,6870.98) 15102.36,6870.98 15102.36,6865.98 cw(c15097.36,6865.98) 15097.36,6860.98 ccw(c15097.36,6855.98) 15092.36,6855.98 15092.36,6824 15101.36,6815 15112.02,6815 ccw(c15112.02,6818) 15115.02,6818 cw(c15118.02,6818) 15118.02,6821 15127.02,6821 cw(c15127.02,6818) 15130.02,6818 ccw(c15133.02,6818) 15133.02,6815 15142.02,6815 ccw(c15142.02,6818) 15145.02,6818 cw(c15148.02,6818) 15148.02,6821 15157.02,6821 cw(c15157.02,6818) 15160.02,6818 ccw(c15163.02,6818) 15163.02,6815 15172.02,6815 ccw(c15172.02,6818) 15175.02,6818 cw(c15178.02,6818) 15178.02,6821 15187.02,6821 cw(c15187.02,6818) 15190.02,6818 ccw(c15193.02,6818) 15193.02,6815 15223.36,6815 15231.68,6806.68 ccw(c15236.98,6811.98) 15242.29,6806.68 15244.18,6808.57 cw(c15249.48,6803.27) 15254.79,6797.96 15252.89,6796.07 ccw(c15258.2,6790.77) 15263.5,6785.46 15265.39,6787.36 cw(c15270.7,6782.05) 15276,6776.75 15274.11,6774.86 ccw(c15279.41,6769.55) 15284.71,6764.25 15286.61,6766.14 cw(c15291.91,6760.84) 15297.21,6755.54 15295.32,6753.64 ccw(c15300.62,6748.34) 15305.93,6743.04 15307.82,6744.93 cw(c15313.12,6739.63) 15318.43,6734.32 15316.53,6732.43 ccw(c15321.84,6727.13) 15316.53,6721.82 15345.63,6692.73 cw(c15341.49,6692.73) 15341.49,6688.59 ccw(c15341.49,6684.46) 15337.36,6684.46 15337.36,6677.73 ccw(c15341.49,6677.73) 15341.49,6673.59 cw(c15341.49,6669.46) 15345.63,6669.46 15345.63,6662.73 cw(c15341.49,6662.73) 15341.49,6658.59 ccw(c15341.49,6654.46) 15337.36,6654.46 15337.36,6647.73 ccw(c15341.49,6647.73) 15341.49,6643.59 cw(c15341.49,6639.46) 15345.63,6639.46 15345.63,6632.73 cw(c15341.49,6632.73) 15341.49,6628.59 ccw(c15341.49,6624.46) 15337.36,6624.46 15337.36,6617.73 ccw(c15341.49,6617.73) 15341.49,6613.59 cw(c15341.49,6609.46) 15345.63,6609.46 U3.51@15345.63,6540.41
TFP410_D10_FPGA: RN23.3 U8.Y14 | length 790.1
  Top Layer w4.7: RN23.3@15091.2,6997.83 15091.2,7019.84 v3(15092.36,7021)
  Top Layer w10: U8.Y14@14705.78,7581.35 v2(14725.46,7561.68)
  L6_SIG2 w5: v2(14725.46,7561.68) 14738.36,7548.78 14738.36,7391 15004.52,7124.83 cw(c14999.77,7120.08) 15004.52,7115.33 ccw(c15009.27,7110.58) 15004.52,7105.83 15005.63,7104.73 ccw(c15010.38,7109.48) 15015.13,7104.73 cw(c15019.88,7099.98) 15024.63,7104.73 15025.74,7103.62 cw(c15020.99,7098.87) 15025.74,7094.12 ccw(c15030.49,7089.37) 15025.74,7084.62 15026.84,7083.51 ccw(c15031.59,7088.26) 15036.34,7083.51 cw(c15041.09,7078.76) 15045.84,7083.51 15046.95,7082.41 cw(c15042.2,7077.66) 15046.95,7072.91 ccw(c15051.7,7068.16) 15046.95,7063.41 15048.06,7062.3 ccw(c15052.81,7067.05) 15057.56,7062.3 cw(c15062.31,7057.55) 15067.06,7062.3 15092.36,7037 v3(15092.36,7021)
TFP410_D11: RN23.5 U3.50 | length 967.3
  Top Layer w4.7: RN23.5@15111.89,6964.17 15111.36,6963.64 15111.36,6943.15 ccw(c15118.86,6943.15) 15118.86,6935.65 15127.86,6935.65 cw(c15127.86,6928.15) 15127.86,6920.65 15118.86,6920.65 ccw(c15118.86,6913.15) 15118.86,6905.65 15127.86,6905.65 cw(c15127.86,6898.15) 15127.86,6890.65 15118.86,6890.65 ccw(c15118.86,6883.15) 15118.86,6875.65 15127.86,6875.65 cw(c15127.86,6868.15) 15127.86,6860.65 15118.86,6860.65 ccw(c15118.86,6853.15) 15111.36,6853.15 15111.36,6842 15121.36,6832 15244.06,6832 15365.31,6710.75 15365.31,6694.07 ccw(c15372.81,6694.07) 15372.81,6686.57 15396.86,6686.57 cw(c15396.86,6679.07) 15396.86,6671.57 15372.81,6671.57 ccw(c15372.81,6664.07) 15372.81,6656.57 15396.86,6656.57 cw(c15396.86,6649.07) 15396.86,6641.57 15372.81,6641.57 ccw(c15372.81,6634.07) 15372.81,6626.57 15396.86,6626.57 cw(c15396.86,6619.07) 15396.86,6611.57 15372.81,6611.57 ccw(c15372.81,6604.07) 15372.81,6596.57 15396.86,6596.57 cw(c15396.86,6589.07) 15396.86,6581.57 15372.81,6581.57 ccw(c15372.81,6574.07) 15365.31,6574.07 U3.50@15365.31,6540.41
TFP410_D11_FPGA: RN23.4 U8.W15 | length 787.6
  Top Layer w4.7: RN23.4@15110.89,6997.83 15110.89,7035.53 v3(15111.36,7036)
  Top Layer w10: U8.W15@14745.16,7620.73 v2(14764.84,7601.05)
  L6_SIG2 w5: v2(14764.84,7601.05) 14749.36,7585.57 14749.36,7398 v3(15111.36,7036)
TFP410_D12: RN4.8 U3.47 | length 988.6
  Top Layer w4.7: RN4.8@15147.83,6964.17 15148.36,6963.64 15148.36,6864 15161.36,6851 15261.36,6851 15268.58,6843.78 cw(c15263.27,6838.48) 15268.58,6833.17 15267.68,6832.28 ccw(c15272.99,6826.98) 15278.29,6821.67 15279.18,6822.57 cw(c15284.49,6817.26) 15289.79,6811.96 15288.9,6811.07 ccw(c15294.2,6805.76) 15299.5,6800.46 15300.4,6801.35 cw(c15305.7,6796.05) 15311,6790.75 15310.11,6789.85 ccw(c15315.41,6784.55) 15320.72,6779.25 15321.61,6780.14 cw(c15326.91,6774.84) 15332.22,6769.53 15331.32,6768.64 ccw(c15336.63,6763.34) 15341.93,6758.03 15342.82,6758.93 cw(c15348.13,6753.62) 15353.43,6748.32 15352.54,6747.43 ccw(c15357.84,6742.12) 15363.14,6736.82 15364.04,6737.71 cw(c15369.34,6732.41) 15374.64,6727.11 15373.75,6726.21 ccw(c15379.05,6720.91) 15384.36,6715.61 15385.25,6716.5 cw(c15390.55,6711.2) 15395.86,6716.5 15420.36,6692 15420.36,6568 15434.39,6553.97 cw(c15429.09,6548.66) 15434.39,6543.36 15422.5,6531.47 ccw(c15427.8,6526.16) 15433.11,6520.86 15445,6532.75 cw(c15450.3,6527.45) 15455.61,6522.15 15443.71,6510.25 ccw(c15449.02,6504.95) 15454.32,6499.65 15466.21,6511.54 cw(c15471.52,6506.24) 15476.82,6511.54 15506.36,6482 15506.36,6448.65 15501.66,6443.95 U3.47@15461.77,6443.95
TFP410_D12_FPGA: RN4.1 U8.AB15 | length 671.6
  Top Layer w4.7: v3(15146.36,7021) 15147.83,7019.53 RN4.1@15147.83,6997.83
  Top Layer w10: U8.AB15@14745.16,7502.6 v2(14764.84,7482.92)
  L6_SIG2 w5: v2(14764.84,7482.92) 14764.84,7402.52 v3(15146.36,7021)
TFP410_D13: RN4.7 U3.46 | length 807.2
  Top Layer w4.7: RN4.7@15167.52,6964.17 15167.36,6964.01 15167.36,6873 15172.36,6868 15276.36,6868 15440.36,6704 15440.36,6576 15528.36,6488 15528.36,6441 15511.63,6424.27 U3.46@15461.77,6424.27
TFP410_D13_FPGA: RN4.2 U8.T16 | length 921.1
  Top Layer w4.7: v3(15167.36,7035) 15167.36,6997.99 RN4.2@15167.52,6997.83
  Top Layer w10: U8.T16@14784.52,7738.84 v2(14804.2,7719.16)
  L6_SIG2 w5: v2(14804.2,7719.16) 14778.36,7693.32 14778.36,7424 v3(15167.36,7035)
TFP410_D14: RN4.6 U3.45 | length 979.1
  Top Layer w4.7: RN4.6@15187.2,6964.17 15186.36,6963.33 15186.36,6896 15196.36,6886 15291.36,6886 15300.24,6877.11 cw(c15295.49,6872.36) 15300.24,6867.61 ccw(c15304.99,6862.86) 15300.24,6858.11 15301.35,6857.01 ccw(c15306.1,6861.76) 15310.85,6857.01 cw(c15315.6,6852.26) 15320.35,6857.01 15321.46,6855.9 cw(c15316.71,6851.15) 15321.46,6846.4 ccw(c15326.21,6841.65) 15321.46,6836.9 15322.56,6835.79 ccw(c15327.31,6840.54) 15332.06,6835.79 cw(c15336.81,6831.04) 15341.56,6835.79 15342.67,6834.69 cw(c15337.92,6829.94) 15342.67,6825.19 ccw(c15347.42,6820.44) 15342.67,6815.69 15343.78,6814.58 ccw(c15348.53,6819.33) 15353.28,6814.58 cw(c15358.03,6809.83) 15362.78,6814.58 15363.88,6813.47 cw(c15359.13,6808.72) 15363.88,6803.97 ccw(c15368.63,6799.22) 15363.88,6794.47 15364.99,6793.37 ccw(c15369.74,6798.12) 15374.49,6793.37 cw(c15379.24,6788.62) 15383.99,6793.37 15385.1,6792.26 cw(c15380.35,6787.51) 15385.1,6782.76 ccw(c15389.85,6778.01) 15385.1,6773.26 15386.2,6772.15 ccw(c15390.95,6776.9) 15395.7,6772.15 cw(c15400.45,6767.4) 15405.2,6772.15 15406.31,6771.05 cw(c15401.56,6766.3) 15406.31,6761.55 ccw(c15411.06,6756.8) 15406.31,6752.05 15407.42,6750.94 ccw(c15412.17,6755.69) 15416.92,6750.94 cw(c15421.67,6746.19) 15426.42,6750.94 15427.52,6749.83 cw(c15422.77,6745.08) 15427.52,6740.33 ccw(c15432.27,6735.58) 15427.52,6730.83 15428.63,6729.73 ccw(c15433.38,6734.48) 15438.13,6729.73 cw(c15442.88,6724.98) 15447.63,6729.73 15460.36,6717 15460.36,6692.68 cw(c15454.86,6692.68) 15454.86,6687.18 ccw(c15454.86,6681.68) 15449.36,6681.68 15449.36,6677.68 ccw(c15454.86,6677.68) 15454.86,6672.18 cw(c15454.86,6666.68) 15460.36,6666.68 15460.36,6662.68 cw(c15454.86,6662.68) 15454.86,6657.18 ccw(c15454.86,6651.68) 15449.36,6651.68 15449.36,6647.68 ccw(c15454.86,6647.68) 15454.86,6642.18 cw(c15454.86,6636.68) 15460.36,6636.68 15460.36,6632.68 cw(c15454.86,6632.68) 15454.86,6627.18 ccw(c15454.86,6621.68) 15449.36,6621.68 15449.36,6617.68 ccw(c15454.86,6617.68) 15454.86,6612.18 cw(c15454.86,6606.68) 15460.36,6606.68 15460.36,6581 15547.36,6494 15547.36,6433 15518.94,6404.58 U3.45@15461.77,6404.58
TFP410_D14_FPGA: RN4.3 U8.Y16 | length 761.2
  Top Layer w4.7: v3(15186.36,7020) 15187.2,7019.16 RN4.3@15187.2,6997.83
  Top Layer w10: U8.Y16@14784.52,7581.35 v2(14804.2,7561.68)
  L6_SIG2 w5: v2(14804.2,7561.68) 14791.05,7548.54 14791.05,7434.3 15186.36,7039 v3(15186.36,7020)
TFP410_D15: RN4.5 U3.44 | length 1064.9
  Top Layer w4.7: RN4.5@15206.89,6964.17 15206.89,6911.47 15216.36,6902 15228.36,6902 ccw(c15228.36,6909.5) 15235.86,6909.5 15235.86,6951.5 cw(c15243.36,6951.5) 15250.86,6951.5 15250.86,6909.5 ccw(c15258.36,6909.5) 15265.86,6909.5 15265.86,6951.5 cw(c15273.36,6951.5) 15280.86,6951.5 15280.86,6909.5 ccw(c15288.36,6909.5) 15288.36,6902 15311.36,6902 15479.36,6734 15479.36,6587 15564.36,6502 15564.36,6424 15525.26,6384.9 U3.44@15461.77,6384.9
TFP410_D15_FPGA: RN4.4 U8.AB16 | length 679.7
  Top Layer w4.7: v3(15206.36,7034) 15206.36,6998.36 RN4.4@15206.89,6997.83
  Top Layer w10: U8.AB16@14784.52,7502.6 v2(14804.2,7482.92)
  L6_SIG2 w5: v2(14804.2,7482.92) 14804.2,7443.16 15206.36,7041 v3(15206.36,7034)
TFP410_D16: RN5.8 U3.43 | length 779.6
  Top Layer w4.7: RN5.8@15371.83,6964.17 15370.36,6962.7 15370.36,6890 15500.36,6760 15500.36,6594 15583.36,6511 15583.36,6416 15532.57,6365.21 U3.43@15461.77,6365.21
TFP410_D16_FPGA: RN5.1 U8.AA16 | length 988.2
  Top Layer w4.7: RN5.1@15371.83,6997.83 15371.83,7020.47 v3(15372.36,7021)
  Top Layer w10: U8.AA16@14784.52,7542 v2(14804.2,7522.32)
  L6_SIG2 w5: v2(14804.2,7522.32) 14819.36,7507.16 14819.36,7446 15204.36,7061 15241.76,7061 cw(c15241.76,7053.5) 15249.26,7053.5 15249.26,7033.5 ccw(c15256.76,7033.5) 15264.26,7033.5 15264.26,7053.5 cw(c15271.76,7053.5) 15279.26,7053.5 15279.26,7033.5 ccw(c15286.76,7033.5) 15294.26,7033.5 15294.26,7053.5 cw(c15301.76,7053.5) 15301.76,7061 15351.36,7061 15372.36,7040 v3(15372.36,7021)
TFP410_D17: RN5.7 U3.42 | length 806.7
  Top Layer w4.7: RN5.7@15391.52,6964.17 15391.52,6893.84 15517.36,6768 15517.36,6604 15598.36,6523 15598.36,6404 15539.89,6345.53 U3.42@15461.77,6345.53
TFP410_D17_FPGA: RN5.2 U8.Y17 | length 921.6
  Top Layer w4.7: v3(15391.36,7036) 15391.52,7035.84 RN5.2@15391.52,6997.83
  Top Layer w10: U8.Y17@14823.89,7581.35 v2(14843.57,7561.68)
  L6_SIG2 w5: v2(14843.57,7561.68) 14830.36,7548.47 14830.36,7455 15206.36,7079 15363.36,7079 15391.36,7051 v3(15391.36,7036)
TFP410_D18: RN5.6 U3.41 | length 982.8
  Top Layer w4.7: RN5.6@15411.2,6964.17 15410.36,6963.33 15410.36,6902 15537.36,6775 15537.36,6747.01 ccw(c15541.86,6747.01) 15541.86,6742.51 cw(c15541.86,6738.01) 15546.36,6738.01 15546.36,6732.01 cw(c15541.86,6732.01) 15541.86,6727.51 15532.86,6727.51 ccw(c15532.86,6723.01) 15528.36,6723.01 15528.36,6717.01 ccw(c15532.86,6717.01) 15532.86,6712.51 15541.86,6712.51 cw(c15541.86,6708.01) 15546.36,6708.01 15546.36,6702.01 cw(c15541.86,6702.01) 15541.86,6697.51 15532.86,6697.51 ccw(c15532.86,6693.01) 15528.36,6693.01 15528.36,6687.01 ccw(c15532.86,6687.01) 15532.86,6682.51 15541.86,6682.51 cw(c15541.86,6678.01) 15546.36,6678.01 15546.36,6672.01 cw(c15541.86,6672.01) 15541.86,6667.51 15532.86,6667.51 ccw(c15532.86,6663.01) 15528.36,6663.01 15528.36,6657.01 ccw(c15532.86,6657.01) 15532.86,6652.51 cw(c15532.86,6648.01) 15537.36,6648.01 15537.36,6614 15548.98,6602.38 cw(c15544.98,6598.38) 15548.98,6594.38 ccw(c15552.98,6590.38) 15548.98,6586.38 15551.58,6583.77 ccw(c15555.58,6587.77) 15559.58,6583.77 15567.58,6591.77 cw(c15571.58,6587.77) 15575.58,6591.77 15578.19,6589.17 cw(c15574.19,6585.17) 15578.19,6581.17 15570.19,6573.17 ccw(c15574.19,6569.17) 15570.19,6565.17 15572.8,6562.56 ccw(c15576.8,6566.56) 15580.8,6562.56 15588.8,6570.56 cw(c15592.8,6566.56) 15596.8,6570.56 15599.4,6567.95 cw(c15595.4,6563.95) 15599.4,6559.95 ccw(c15603.4,6555.95) 15599.4,6551.95 15613.36,6538 15613.36,6392 15547.2,6325.84 U3.41@15461.77,6325.84
TFP410_D18_FPGA: RN5.3 U8.AB17 | length 845.9
  Top Layer w4.7: v3(15410.36,7021) 15411.2,7020.16 RN5.3@15411.2,6997.83
  Top Layer w10: U8.AB17@14823.89,7502.6 v2(14843.57,7482.92)
  L6_SIG2 w5: v2(14843.57,7482.92) 14843.57,7457.79 15206.36,7095 15373.36,7095 15410.36,7058 v3(15410.36,7021)
TFP410_D19: RN5.5 U3.40 | length 862.8
  Top Layer w4.7: RN5.5@15430.89,6964.17 15430.89,6903.47 15556.36,6778 15556.36,6626 15629.36,6553 15629.36,6383 15552.52,6306.16 U3.40@15461.77,6306.16
TFP410_D19_FPGA: RN5.4 U8.V18 | length 1020.9
  Top Layer w4.7: RN5.4@15430.89,6997.83 15430.89,7033.53 v3(15431.36,7034)
  Top Layer w10: U8.V18@14863.26,7660.1 v2(14882.94,7640.42)
  L6_SIG2 w5: v2(14882.94,7640.42) 14857.36,7614.84 14857.36,7462 15209.36,7110 15383.36,7110 15431.36,7062 v3(15431.36,7034)
TFP410_D20: RN6.8 U3.39 | length 888.2
  Top Layer w4.7: U3.39@15461.77,6286.47 15560.83,6286.47 15648.36,6374 15648.36,6565 15577.36,6636 15577.36,6793 15466.83,6903.53 RN6.8@15466.83,6964.17
TFP410_D20_FPGA: RN6.1 U8.W18 | length 994.1
  Top Layer w4.7: RN6.1@15466.83,6997.83 15466.83,7018.47 v3(15467.36,7019)
  Top Layer w10: U8.W18@14863.26,7620.73 v2(14882.94,7601.05)
  L6_SIG2 w5: v2(14882.94,7601.05) 14869.36,7587.47 14869.36,7466 15211.36,7124 15398.36,7124 15467.36,7055 v3(15467.36,7019)
TFP410_D21: RN6.7 U3.38 | length 921.7
  Top Layer w4.7: U3.38@15461.77,6266.79 15571.15,6266.79 15666.36,6362 15666.36,6578 15596.36,6648 15596.36,6800 15485.36,6911 15485.36,6963.01 RN6.7@15486.52,6964.17
TFP410_D21_FPGA: RN6.2 U8.AB18 | length 880.7
  Top Layer w4.7: v3(15486.36,7034) 15486.36,6997.99 RN6.2@15486.52,6997.83
  Top Layer w10: U8.AB18@14863.26,7502.6 v2(14882.94,7482.92)
  L6_SIG2 w5: v2(14882.94,7482.92) 14882.94,7469.42 15214.36,7138 15415.36,7138 15486.36,7067 v3(15486.36,7034)
TFP410_D22: RN6.6 U3.37 | length 954.5
  Top Layer w4.7: U3.37@15461.77,6247.1 15579.46,6247.1 15687.36,6355 15687.36,6587 15616.36,6658 15616.36,6803 15506.36,6913 15506.36,6964.01 RN6.6@15506.2,6964.17
TFP410_D22_FPGA: RN6.3 U8.AA18 | length 938.9
  Top Layer w4.7: RN6.3@15506.2,6997.83 15506.2,7018.84 v3(15506.36,7019)
  Top Layer w10: U8.AA18@14863.26,7542 v2(14882.94,7522.32)
  L6_SIG2 w5: v2(14882.94,7522.32) 14896.36,7508.9 14896.36,7472 15217.36,7151 15436.36,7151 15506.36,7081 v3(15506.36,7019)
TFP410_D23: RN6.5 U3.36 | length 989.2
  Top Layer w4.7: U3.36@15461.77,6227.42 15590.78,6227.42 15707.36,6344 15707.36,6596 15636.36,6667 15636.36,6804 15525.89,6914.47 RN6.5@15525.89,6964.17
TFP410_D23_FPGA: RN6.4 U8.AB19 | length 895.1
  Top Layer w4.7: RN6.4@15525.89,6997.83 15525.89,7032.53 v3(15526.36,7033)
  Top Layer w10: U8.AB19@14902.63,7502.6 v2(14922.31,7482.92)
  L6_SIG2 w5: v2(14922.31,7482.92) 14922.31,7466.05 15224.36,7164 15449.36,7164 15526.36,7087 v3(15526.36,7033)
TMS: CN2.5 R19.1 | length 202.6
  Bottom Layer w4.7: CN2.5@12932.36,8916 12971.03,8877.33 R19.1@12971.03,8729.37
TXD: R159.1 TP19.1 U104.26 U108.1 | length 413.1
  Top Layer w4.7: U108.1@12582.62,6651 12633.62,6600 12862.84,6600 TP19.1@12864.7,6601.85 ; TP19.1@12864.7,6601.85 R159.1@12864.73,6644.8 12869.15,6649.23 U104.26@12929.09,6649.23
UP_A0: R37.1 U5.N3 U8.H2 | length 1123.8
  Top Layer w4.7: v3(13798.36,8465) 13806.68,8465 13873.36,8398.33 13873.36,8229 13884.63,8217.73 U5.N3@13915.35,8217.73 v2(13931.09,8233.48)
  Top Layer w7.9: v2(14213.67,8073.47) U8.H2@14233.34,8053.8
  L3_SIG1 w5: v2(13931.09,8233.48) 13920.4,8233.48 13917.81,8230.89 cw(c13912.81,8230.89) 13912.81,8225.89 13900.86,8225.89 ccw(c13900.86,8220.89) 13900.86,8215.89 13912.81,8215.89 cw(c13912.81,8210.89) 13912.81,8205.89 13900.86,8205.89 ccw(c13900.86,8200.89) 13900.86,8195.89 13912.81,8195.89 cw(c13912.81,8190.89) 13912.81,8185.89 13900.86,8185.89 ccw(c13900.86,8180.89) 13900.86,8175.89 13912.81,8175.89 cw(c13912.81,8170.89) 13912.81,8165.89 13900.86,8165.89 ccw(c13900.86,8160.89) 13900.86,8155.89 13912.81,8155.89 cw(c13912.81,8150.89) 13912.81,8145.89 13900.86,8145.89 ccw(c13900.86,8140.89) 13900.86,8135.89 13912.81,8135.89 cw(c13912.81,8130.89) 13917.81,8130.89 13917.81,8130.2 13925.71,8122.3 13985.44,8122.3 cw(c13985.44,8117.3) 13990.44,8117.3 13990.44,8113.24 ccw(c13995.44,8113.24) 14000.44,8113.24 14000.44,8117.3 cw(c14005.44,8117.3) 14010.44,8117.3 14010.44,8113.24 ccw(c14015.44,8113.24) 14020.44,8113.24 14020.44,8117.3 cw(c14025.44,8117.3) 14030.44,8117.3 14030.44,8113.24 ccw(c14035.44,8113.24) 14040.44,8113.24 14040.44,8117.3 cw(c14045.44,8117.3) 14050.44,8117.3 14050.44,8113.24 ccw(c14055.44,8113.24) 14060.44,8113.24 14060.44,8117.3 cw(c14065.44,8117.3) 14070.44,8117.3 14070.44,8113.24 ccw(c14075.44,8113.24) 14080.44,8113.24 14080.44,8117.3 cw(c14085.44,8117.3) 14090.44,8117.3 14090.44,8113.24 ccw(c14095.44,8113.24) 14100.44,8113.24 14100.44,8117.3 cw(c14105.44,8117.3) 14105.44,8122.3 14135.35,8122.3 14162.11,8095.55 14191.59,8095.55 v2(14213.67,8073.47)
  Bottom Layer w4.7: R37.1@13786.36,8486.96 13786.36,8477 v3(13798.36,8465)
UP_A1: R42.1 U5.P7 U8.H1 | length 1171.7
  Top Layer w4.7: R42.1@13626.36,8486.96 13626.36,8391 13643.36,8374 13762.36,8374 13805.36,8331 13805.36,8260 13794.59,8249.23 U5.P7@13789.37,8249.23 v2(13773.62,8264.98)
  Top Layer w7.9: v2(14174.29,8073.47) U8.H1@14193.96,8053.8
  L3_SIG1 w5: v2(13773.62,8264.98) 13789.78,8248.82 cw(c13786.25,8245.28) 13789.78,8241.75 13789.29,8241.25 ccw(c13792.82,8237.72) 13796.36,8234.18 13796.85,8234.67 cw(c13800.39,8231.14) 13803.92,8227.6 13790.02,8213.7 ccw(c13793.56,8210.17) 13797.09,8206.63 13810.99,8220.53 cw(c13814.53,8217) 13818.07,8213.46 13804.16,8199.56 ccw(c13807.7,8196.02) 13811.23,8192.49 13825.14,8206.39 cw(c13828.67,8202.85) 13832.21,8199.32 13818.31,8185.42 ccw(c13821.84,8181.88) 13825.38,8178.35 13839.28,8192.25 cw(c13842.81,8188.71) 13846.35,8185.18 13832.45,8171.27 ccw(c13835.98,8167.74) 13839.52,8164.2 13853.42,8178.11 cw(c13856.96,8174.57) 13860.49,8178.11 13878.95,8159.65 13878.95,8100.58 13886.74,8092.79 14135.93,8092.79 14154.68,8074.04 14173.71,8074.04 v2(14174.29,8073.47)
UP_A2: R41.1 U5.P3 U8.H5 | length 1046.9
  Top Layer w4.7: R41.1@13826.36,8486.96 13826.36,8466.05 13884.36,8408.05 13884.36,8256 13891.13,8249.23 U5.P3@13915.35,8249.23 v2(13931.09,8264.98)
  Top Layer w7.9: v2(14331.79,8073.47) U8.H5@14351.46,8053.8
  L3_SIG1 w5: v2(13931.09,8264.98) 13941.94,8264.98 13959.87,8247.04 14062.73,8247.04 ccw(c14066.27,8250.58) 14069.8,8247.04 14078.11,8255.35 cw(c14081.64,8251.81) 14085.18,8248.28 14076.87,8239.97 ccw(c14080.41,8236.44) 14083.95,8232.9 14092.25,8241.2 cw(c14095.78,8237.67) 14099.32,8234.13 14091.02,8225.83 ccw(c14094.55,8222.3) 14098.09,8218.76 14106.39,8227.06 cw(c14109.93,8223.53) 14113.46,8219.99 14105.16,8211.69 ccw(c14108.69,8208.15) 14105.16,8204.62 14105.35,8204.42 14268.65,8204.42 cw(c14268.65,8199.42) 14273.65,8199.42 14273.65,8193.12 ccw(c14278.65,8193.12) 14283.65,8193.12 14283.65,8199.42 cw(c14288.65,8199.42) 14288.65,8204.42 14295.56,8204.42 14305.39,8194.59 14305.39,8182.75 ccw(c14310.39,8182.75) 14310.39,8177.75 14311.99,8177.75 cw(c14311.99,8172.75) 14311.99,8167.75 14310.39,8167.75 ccw(c14310.39,8162.75) 14310.39,8157.75 14311.99,8157.75 cw(c14311.99,8152.75) 14311.99,8147.75 14310.39,8147.75 ccw(c14310.39,8142.75) 14310.39,8137.75 14311.99,8137.75 cw(c14311.99,8132.75) 14311.99,8127.75 14310.39,8127.75 ccw(c14310.39,8122.75) 14305.39,8122.75 14305.39,8115.57 14330.07,8090.89 14330.07,8075.19 v2(14331.79,8073.47)
UP_A3: R36.1 U5.N2 U8.K6 | length 1147.2
  Top Layer w4.7: v3(13920.36,8463) 13924.29,8459.07 13924.29,8393.07 13967.36,8350 14007.36,8350 14032.06,8325.3 14032.06,8270.7 14027.62,8266.26 v3(14022.6,8266.26) ; U5.N2@13946.85,8217.73 v2(13962.59,8233.48)
  Top Layer w7.9: v2(14371.15,7994.73) U8.K6@14390.82,7975.06
  L6_SIG2 w5: v2(13962.59,8233.48) 13966.8,8233.48 13983.88,8216.4 14093.25,8216.4 14100.36,8209.29 14224.63,8209.29 ccw(c14224.63,8214.29) 14229.63,8214.29 14229.63,8237.69 cw(c14234.63,8237.69) 14239.63,8237.69 14239.63,8214.29 ccw(c14244.63,8214.29) 14249.63,8214.29 14249.63,8237.69 cw(c14254.63,8237.69) 14259.63,8237.69 14259.63,8214.29 ccw(c14264.63,8214.29) 14264.63,8209.29 14293.73,8209.29 14311.27,8191.75 14311.27,8028.09 14324.96,8014.39 14352.76,8014.39 14371.15,7996.01 v2(14371.15,7994.73)
  Bottom Layer w4.7: R36.1@13906.36,8486.96 13906.36,8477 v3(13920.36,8463) ; v2(13962.59,8233.48) 13962.83,8233.48 13981.37,8252.01 14004.71,8252.01 14018.96,8266.26 v3(14022.6,8266.26)
UP_A4: R43.1 U5.P8 U8.F3 | length 1138.5
  Top Layer w4.7: R43.1@13546.36,8486.96 13546.36,8376 v3(13640.36,8282) ; v2(13742.12,8264.98) U5.P8@13757.87,8249.23
  Top Layer w7.9: v2(14253.04,8152.21) U8.F3@14272.71,8132.53
  L3_SIG1 w5: v3(13640.36,8282) 13723.36,8282 13740.38,8264.98 v2(13742.12,8264.98)
  Bottom Layer w4.7: v2(13742.12,8264.98) 13756.15,8250.94 13859.41,8250.94 13925.36,8185 13984.36,8185 14003.45,8165.9 14111.44,8165.9 cw(c14111.44,8160.9) 14116.44,8160.9 14116.44,8122.09 ccw(c14121.44,8122.09) 14126.44,8122.09 14126.44,8160.9 cw(c14131.44,8160.9) 14136.44,8160.9 14136.44,8122.09 ccw(c14141.44,8122.09) 14146.44,8122.09 14146.44,8160.9 cw(c14151.44,8160.9) 14151.44,8165.9 14239.34,8165.9 v2(14253.04,8152.21)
